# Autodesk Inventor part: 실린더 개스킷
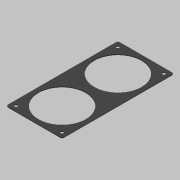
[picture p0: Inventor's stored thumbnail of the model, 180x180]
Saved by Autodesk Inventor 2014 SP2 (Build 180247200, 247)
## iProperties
Created: 2019-08
Part Number: 실린더 개스킷
Material: 고무
Document SubType Name: Modeling
Designer: mduedu
Density: 0.93 g/cm^3
Appearance: 고무 - 검은색 - 버전 1.1
Mass: 5.78528 g
Surface Area: 134.615 cm^2
Volume: 6.22073 cm^3
Author: mduedu
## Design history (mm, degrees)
sketch "스케치1"
  geometry: L1 (42.5, -42.5)-(-42.5, -42.5); L2 (-42.5, -42.5)-(-42.5, 127.5); L3 (-42.5, 127.5)-(42.5, 127.5); L4 (42.5, 127.5)-(42.5, -42.5); 2 further points
  constraints: 8 end point, 2 parallel, 1 horizontal, 1 midpoint, 1 perpendicular, 1 vertical alignment
  dimensions: "d1" = 85 distance of L1.start L1.end; "d3" = 170 distance of L3.end L1.start; "d4" = 42.5 distance from line of L1 point (0, 0)
extrude "돌출1" new body sketch "스케치1" distance "d5" = 1; taper "d6" = 0 deg
sketch "스케치2"
  geometry: C1 r 36 at (0, 0); C2 r 36 at (0, 85); 1 further point
  constraints: 2 centre point, 1 coincident, 1 vertical alignment
  dimensions: "d7" = 72 diameter of C1; "d8" = 72 diameter of C2; "d9" = 85 distance of C2.centre point (0, 0)
extrude "돌출2" cut sketch "스케치2" stored distance "d10" = 1; taper "d11" = 0 deg
sketch "스케치3"
  geometry: L1 (-35, -35)-(35, -35); L2 (35, -35)-(35, 35); L3 (35, 35)-(-35, 35); L4 (-35, 35)-(-35, -35); L5 (-35, -35)-(35, 35); L6 (35, -35)-(-35, 35); L7 (-35, 50)-(35, 50); L8 (35, 50)-(35, 120); L9 (35, 120)-(-35, 120); L10 (-35, 120)-(-35, 50); L11 (-35, 50)-(35, 120); L12 (35, 50)-(-35, 120); C1 r 36 at (0, 85) reference; 5 further points
  constraints: 24 end point, 4 coincident, 4 midpoint, 4 parallel, 2 horizontal, 2 perpendicular
  dimensions: "d12" = 70 distance of L3.end L2.end; "d13" = 70 distance of L2.end L1.end; "d14" = 70 distance of L9.end L8.end; "d15" = 70 distance of L8.end L7.end
hole "구멍1" sketch "스케치3" at (35, -35), (-35, -35), (-35, 120), (35, 120) diameter "d16" = 5; stored, may be unused: countersink angle "d20" = 90 deg, drill point angle "d22" = 118 deg; dims "d17" = 6, "d18" = 4, "d19" = 2, "d21" = 8
fillet "모깎기1" dims "d23" = 3
node "솔리드2"
node "솔리드1"
